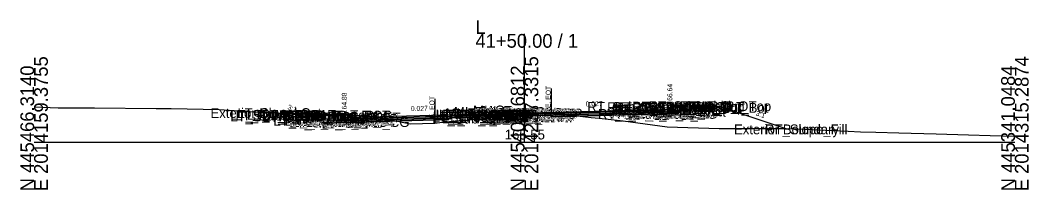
# Model space of a CAD drawing. Extents: x -26 to 4203, y -10 to 9526.
# Drawn here: x 2997.2 to 3202.8, y 1490.3 to 1524.8 of the extents above; entities that cross this region are included whole.
import ezdxf

# ---------------------------------------------------------------- set-up
doc = ezdxf.new("R2010")
doc.units = 0
for name, color, linetype in [('Default', 7, 'Continuous'), ('Exist CMT Pavement', 7, 'Continuous'), ('Exist Cross Section Cell', 7, 'Continuous'), ('Exist XS Center Line Elevation Label', 7, 'Continuous'), ('Exist XS Ground Line', 7, 'Continuous'), ('Prop CMT Conc Surface', 7, 'Continuous'), ('Prop CMT Concrete Structures', 7, 'Continuous'), ('Prop CMT Pvmt Course 1', 7, 'Continuous'), ('Prop CMT Pvmt Course 1 CG', 7, 'Continuous'), ('Prop CMT Pvmt Course 2', 7, 'Continuous'), ('Prop CMT Pvmt Course 3', 7, 'Continuous'), ('Prop CMT Pvmt Surface', 7, 'Continuous'), ('Prop CMT Slope Grass', 7, 'Continuous'), ('Prop CMT Subgrade Earthwork', 7, 'Continuous'), ('Prop XS Hydro Elevations', 7, 'Continuous'), ('Prop XS Label Text', 7, 'Continuous'), ('Prop XS SE Text', 7, 'Continuous'), ('Prop XS Side Slope Text', 7, 'Continuous'), ('Scratch_Level_0', 7, 'Continuous')]:
    doc.layers.add(name, color=color, linetype=linetype)

msp = doc.modelspace()

# ---------------------------------------------------------------- linework, layer by layer
at = {"layer": 'Exist CMT Pavement'}
for p, q in [((3100, 1505.55), (3101.76, 1505.67)), ((3101.76, 1505.67), (3104.09, 1505.85)), ((3104.09, 1505.85), (3105.42, 1505.92)), ((3081.73, 1503.85), (3082.74, 1504.01)), ((3082.74, 1504.01), (3083.54, 1504.08)), ((3083.54, 1504.08), (3085.88, 1504.31)), ((3085.88, 1504.31), (3090.05, 1504.7)), ((3090.05, 1504.7), (3093.14, 1504.98)), ((3093.14, 1504.98), (3095.02, 1505.13)), ((3095.02, 1505.13), (3097.81, 1505.36)), ((3097.81, 1505.36), (3100, 1505.55))]:
    msp.add_line(p, q, dxfattribs=at)
at = {"layer": 'Exist Cross Section Cell'}
for p, q in [((3100, 1500), (3100, 1522.02)), ((3000, 1500), (3100, 1500)), ((3100, 1500), (3200, 1500))]:
    msp.add_line(p, q, dxfattribs=at)
at = {"layer": 'Exist XS Ground Line'}
msp.add_lwpolyline([(3000, 1507.18), (3004.91, 1507.02), (3012.31, 1507.01), (3024.88, 1506.88), (3027.95, 1506.86), (3037.71, 1506.62), (3043.92, 1506.23), (3050.54, 1505.92), (3054.7, 1505.92), (3060, 1505.69), (3069.25, 1505.27), (3076.7, 1503.72), (3081.73, 1503.85), (3082.74, 1504.01), (3083.54, 1504.08), (3085.88, 1504.31), (3086.33, 1504.36), (3086.71, 1504.4), (3090.05, 1504.7), (3093.14, 1504.98), (3093.84, 1505.03), (3095.02, 1505.13), (3096.34, 1505.24), (3097.81, 1505.36), (3099.51, 1505.51), (3100, 1505.55), (3101.76, 1505.67), (3102.75, 1505.75), (3104.09, 1505.85), (3104.65, 1505.88), (3105.42, 1505.92), (3109.03, 1505.54), (3113.6, 1505.05), (3115.23, 1504.87), (3120.09, 1504.31), (3129.11, 1503.1), (3139.7, 1502.78), (3140.34, 1502.77), (3142.85, 1502.77), (3153.17, 1502.78), (3155.7, 1502.73), (3161.41, 1502.46), (3166, 1502.27), (3168.52, 1502.1), (3171.67, 1502.02), (3176.33, 1501.91), (3183.95, 1501.73), (3190.55, 1501.48), (3194.94, 1501.35), (3200, 1501.19)], dxfattribs=at)
at = {"layer": 'Prop CMT Conc Surface'}
for points in [[(3127.64, 1506.67), (3129.64, 1506.64)], [(3129.64, 1506.64), (3129.64, 1507.14), (3130.14, 1507.14)], [(3134.14, 1507.23), (3139.14, 1507.33)], [(3058.75, 1505.47), (3053.75, 1505.57)], [(3063.25, 1504.88), (3063.25, 1505.38), (3062.75, 1505.38)], [(3065.25, 1505.01), (3063.25, 1504.88)]]:
    msp.add_lwpolyline(points, dxfattribs=at)
at = {"layer": 'Prop CMT Concrete Structures'}
for points in [[(3100.87, 1505.96), (3100.86, 1506.12), (3100.11, 1506.37), (3096.44, 1506.45), (3092.76, 1506.14), (3092.01, 1505.89), (3092, 1505.72)], [(3092, 1505.72), (3100.87, 1505.96)], [(3127.64, 1506.67), (3129.64, 1506.64), (3129.64, 1507.14), (3130.14, 1507.14)], [(3130.14, 1507.14), (3130.14, 1506.15), (3127.64, 1506.09)], [(3127.64, 1506.09), (3127.64, 1506.67)], [(3139.14, 1507.33), (3134.14, 1507.23)], [(3134.14, 1507.23), (3134.14, 1506.9)], [(3134.14, 1506.9), (3139.14, 1507)], [(3139.14, 1507), (3139.14, 1507.33)], [(3053.75, 1505.23), (3053.75, 1505.57)], [(3053.75, 1505.57), (3058.75, 1505.47)], [(3058.75, 1505.13), (3053.75, 1505.23)], [(3058.75, 1505.47), (3058.75, 1505.13)], [(3065.25, 1505.01), (3063.25, 1504.88), (3063.25, 1505.38), (3062.75, 1505.38)], [(3062.75, 1505.38), (3062.75, 1504.36), (3065.25, 1504.43)], [(3065.25, 1504.43), (3065.25, 1505.01)]]:
    msp.add_lwpolyline(points, dxfattribs=at)
at = {"layer": 'Prop CMT Pvmt Course 1'}
for points in [[(3092, 1505.72), (3065.25, 1505.01)], [(3092, 1505.72), (3100.87, 1505.96)], [(3092, 1505.47), (3092, 1505.72)], [(3092, 1505.47), (3092, 1505.72)], [(3100.87, 1505.71), (3092, 1505.47)], [(3100.87, 1505.96), (3127.64, 1506.67)], [(3127.64, 1506.42), (3100.87, 1505.71)], [(3100.87, 1505.96), (3100.87, 1505.71)], [(3100.87, 1505.71), (3100.87, 1505.96)], [(3127.64, 1506.67), (3127.64, 1506.42)], [(3065.25, 1504.76), (3092, 1505.47)], [(3065.25, 1505.01), (3065.25, 1504.76)]]:
    msp.add_lwpolyline(points, dxfattribs=at)
for points in [[(3092, 1505.47), (3092, 1505.6), (3092, 1505.6), (3092, 1505.47)], [(3100.87, 1505.71), (3100.87, 1505.83), (3100.87, 1505.83), (3100.87, 1505.71)]]:
    msp.add_lwpolyline(points, close=True, dxfattribs=at)
at = {"layer": 'Prop CMT Pvmt Course 1 CG'}
for points in [[(3127.64, 1506.09), (3130.64, 1506.17), (3130.96, 1505.84)], [(3127.64, 1505.75), (3127.64, 1506.09)], [(3130.96, 1505.84), (3127.64, 1505.75)], [(3065.25, 1504.43), (3062.25, 1504.35), (3061.91, 1504)], [(3061.91, 1504), (3065.25, 1504.09)], [(3065.25, 1504.09), (3065.25, 1504.43)]]:
    msp.add_lwpolyline(points, dxfattribs=at)
at = {"layer": 'Prop CMT Pvmt Course 2'}
for points in [[(3092, 1505.47), (3100.87, 1505.71)], [(3100.87, 1505.71), (3127.64, 1506.42)], [(3127.64, 1506.09), (3100.87, 1505.37)], [(3100.87, 1505.71), (3100.87, 1505.37)], [(3100.87, 1505.37), (3100.87, 1505.71)], [(3127.64, 1506.42), (3127.64, 1506.09)], [(3092, 1505.47), (3065.25, 1504.76)], [(3065.25, 1504.43), (3092, 1505.14)], [(3065.25, 1504.76), (3065.25, 1504.43)], [(3092, 1505.14), (3092, 1505.47)], [(3092, 1505.14), (3092, 1505.47)], [(3100.87, 1505.37), (3092, 1505.14)]]:
    msp.add_lwpolyline(points, dxfattribs=at)
at = {"layer": 'Prop CMT Pvmt Course 3'}
for points in [[(3100.87, 1505.37), (3127.64, 1506.09)], [(3127.64, 1505.75), (3105.42, 1505.16)], [(3127.64, 1506.09), (3127.64, 1505.75)], [(3092, 1505.14), (3065.25, 1504.43)], [(3065.25, 1504.09), (3081.73, 1504.53)], [(3065.25, 1504.43), (3065.25, 1504.09)], [(3092, 1505.14), (3100.87, 1505.37)]]:
    msp.add_lwpolyline(points, dxfattribs=at)
at = {"layer": 'Prop CMT Pvmt Surface'}
for points in [[(3092, 1505.72), (3065.25, 1505.01)], [(3092, 1505.72), (3100.87, 1505.96)], [(3100.87, 1505.96), (3127.64, 1506.67)]]:
    msp.add_lwpolyline(points, dxfattribs=at)
at = {"layer": 'Prop CMT Slope Grass'}
for points in [[(3062.75, 1505.38), (3053.25, 1505.57), (3052.18, 1505.92)], [(3130.14, 1507.14), (3139.64, 1507.33), (3153.27, 1502.79)]]:
    msp.add_lwpolyline(points, dxfattribs=at)
at = {"layer": 'Prop CMT Subgrade Earthwork'}
for p, q in [((3105.42, 1505.16), (3105.42, 1505.92)), ((3081.73, 1504.53), (3081.73, 1503.85))]:
    msp.add_line(p, q, dxfattribs=at)
for points in [[(3105.42, 1505.16), (3127.64, 1505.75)], [(3127.64, 1505.75), (3130.96, 1505.84), (3132.31, 1507.18)], [(3065.25, 1504.09), (3061.91, 1504), (3060.49, 1505.42)], [(3081.73, 1504.53), (3065.25, 1504.09)]]:
    msp.add_lwpolyline(points, dxfattribs=at)
at = {"layer": 'Prop XS Label Text'}
for p, q in [((3105.42, 1510.92), (3105.42, 1505.92)), ((3081.73, 1508.85), (3081.73, 1503.85))]:
    msp.add_line(p, q, dxfattribs=at)

# ---------------------------------------------------------------- texts
at = {"layer": 'Default'}
msp.add_text('-', height=0.0001, dxfattribs=at).set_placement((3000, 1500))
at = {"layer": 'Exist Cross Section Cell'}
for s, p in [('L', (3090, 1522.02)), ('41+50.00 / 1', (3090, 1519.22))]:
    msp.add_text(s, height=2.8, dxfattribs=at).set_placement(p)
for s, p in [('E 2014159.3755', (3002.8, 1490)), ('E 2014237.3315', (3102.8, 1490)), ('E 2014315.2874', (3202.8, 1490)), ('N 445466.3140', (3000, 1490)), ('N 445403.6812', (3100, 1490)), ('N 445341.0484', (3200, 1490))]:
    msp.add_text(s, height=2.8, rotation=90, dxfattribs=at).set_placement(p)
at = {"layer": 'Exist XS Center Line Elevation Label'}
msp.add_text('165.55', height=2, dxfattribs=at).set_placement((3095.98, 1500.55))
at = {"layer": 'Prop XS Hydro Elevations'}
for s, p in [('164.88', (3063.75, 1505.88)), ('166.64', (3130.14, 1507.64))]:
    msp.add_text(s, height=1, rotation=90, dxfattribs=at).set_placement(p)
at = {"layer": 'Prop XS Label Text'}
for p in [(3105.32, 1506.95), (3081.63, 1504.87)]:
    msp.add_text('E. EOT', height=1, rotation=90, dxfattribs=at).set_placement(p)
at = {"layer": 'Prop XS SE Text'}
for rotation, p in [(1.5217, (3112.48, 1507.27)), (1.5226, (3076.84, 1506.32))]:
    msp.add_text('0.027', height=1, rotation=rotation, dxfattribs=at).set_placement(p)
at = {"layer": 'Prop XS Side Slope Text'}
for p in [(3051.59, 1506.75), (3147.08, 1505.48)]:
    msp.add_text('3:1', height=1, rotation=341.5651, dxfattribs=at).set_placement(p)
at = {"layer": 'Scratch_Level_0'}
for s, p in [('RT_Sub_Trench_Out_DLT', (3112.83, 1506.18)), ('RT_CG_Top_Face', (3116.85, 1506.14)), ('RT_CG_Top_Gut', (3117.83, 1505.64)), ('RT_PV1_OEOT', (3118.33, 1505.67)), ('RT_CG_Top_BOC', (3118.38, 1506.14)), ('RT_SDWK_In_Top', (3121.95, 1506.23)), ('RT_SDWK_In_Bot', (3121.98, 1505.9)), ('RT_SDWK_Out_Top', (3125.33, 1506.33)), ('RT_SDWK_Out_Bot', (3125.36, 1506)), ('RT_Shld_O', (3131.68, 1506.32)), ('CSLP_Pnt', (3132.51, 1506.33)), ('Exterior Boundary', (3035.97, 1504.92)), ('LT_SDWK_Out_Top', (3039.99, 1504.57)), ('LT_SDWK_Out_Bot', (3040.02, 1504.23)), ('LT_Sub_Trench_Out_DLT', (3041.06, 1504.42)), ('LT_Slope_Cut', (3041.46, 1504.92)), ('LT_CSLP_Pnt', (3043.42, 1504.57)), ('LT_SDWK_In_Top', (3046.61, 1504.47)), ('LT_SDWK_In_Bot', (3046.64, 1504.13)), ('LT_CG_Top_Face', (3050.51, 1504.38)), ('LT_CG_Top_BOC', (3051.03, 1504.38)), ('LT_CG_Top_Gut', (3051.49, 1503.88)), ('LT_PV2_OEOT', (3055.42, 1503.76)), ('LT_PV1_OEOT', (3055.99, 1504.01)), ('LT_Sub_OEEOP', (3081.21, 1503.8)), ('LT_PV2_OEEOP', (3081.31, 1504.47)), ('LT_PV3_OEEOP', (3081.31, 1504.14)), ('LT_PV1_OEEOP', (3081.87, 1504.6)), ('LT_PV2_IEEOP', (3081.95, 1504.47)), ('LT_PV1_IEEOP', (3082.52, 1504.6)), ('LT_PV2_PGL1', (3082.88, 1504.47)), ('LT_PV3_PGL1', (3082.88, 1504.14)), ('LT_PV2_PGL', (3083.21, 1504.47)), ('LT_PV4_PGL', (3083.21, 1503.81)), ('LT_PV1_PGL', (3083.78, 1504.72)), ('MI_Face In', (3083.9, 1504.89)), ('MI_Top In', (3085.61, 1505.14)), ('MI_Crown', (3089.51, 1505.45)), ('RT_Sub_OEEOP', (3090.04, 1504.04)), ('RT_PV2_OEEOP', (3090.13, 1504.71)), ('RT_PV3_OEEOP', (3090.13, 1504.37)), ('RT_PV1_OEEOP', (3090.7, 1504.83)), ('RT_PV2_IEEOP', (3090.78, 1504.71)), ('MI_Face Out', (3091.13, 1505.12)), ('MI_Top Out', (3091.34, 1505.37)), ('RT_PV1_IEEOP', (3091.35, 1504.83)), ('RT_PV2_PGL1', (3091.71, 1504.71)), ('RT_PV3_PGL1', (3091.71, 1504.37)), ('RT_PV2_PGL', (3092.04, 1504.71)), ('RT_PV4_PGL', (3092.04, 1504.04)), ('MI_Bot Out', (3092.13, 1504.96)), ('RT_PV1_PGL', (3092.61, 1504.96)), ('RT_Sub_OEOT_CG', (3114.96, 1504.75)), ('RT_CG1_Shelf_Out', (3117.14, 1505.17)), ('RT_CG_Bot_IE', (3117.51, 1505.09)), ('RT_Sub_OEOT', (3117.67, 1504.75)), ('RT_PV2_OEOT', (3117.77, 1505.42)), ('RT_PV3_OEOT', (3117.77, 1505.09)), ('RT_CG_Bot_BOC', (3118.41, 1505.15)), ('RT_Sub_OEOP', (3121.03, 1504.84)), ('LT_CG1_Shelf_Out', (3048.8, 1503.35)), ('LT_CG_Bot_BOC', (3051.07, 1503.36)), ('LT_Sub_OEOP', (3052.02, 1503)), ('LT_Sub_OEOT_CG', (3052.62, 1503.09)), ('LT_CG_Bot_IE', (3055.16, 1503.43)), ('LT_Sub_OEOT', (3055.33, 1503.09)), ('LT_PV3_OEOT', (3055.42, 1503.43)), ('Exterior Boundary', (3142.72, 1501.6)), ('RT_Slope_Fill', (3149.05, 1501.6))]:
    msp.add_text(s, height=2, dxfattribs=at).set_placement(p)

doc.saveas('drawing.dxf')
